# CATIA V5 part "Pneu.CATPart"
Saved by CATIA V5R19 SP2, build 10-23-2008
Part number: Pneu
Bounding box of the stored display mesh (mm): x -10 to 50, y -41.955 to 41.955, z -41.99 to 41.99
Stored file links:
  D:\France\IFMA\IAO\Projet\Pneu.CATPart
  D:\France\IFMA\IAO\Projet\pruangdaja_CAO.CATProduct
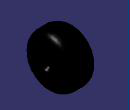
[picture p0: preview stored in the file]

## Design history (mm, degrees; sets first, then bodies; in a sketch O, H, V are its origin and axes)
External parameters (linked from other documents)
  External.Largeur = 10 mm
  External.RayonTrou = 5 mm
Set1
  Plane1: type OffsetPt, RefPlane xy-plane, RefPoint Point1
  Sketch1 on Plane1, origin (0, 0, 0), H (1, 0, 0), V (0, 1, 0)
    line L1 (5, -5) -> (5, -27)
    arc A1 centre (20, -27) radius 15 from (5, -27) to (20, -42) ccw
    line L2 (24.866, -40.5) -> (25.7321, -42)
    line L3 (25.7321, -42) -> (29.2679, -42)
    line L4 (29.2679, -42) -> (30.134, -40.5)
    line L5 (30.134, -40.5) -> (32.134, -40.5)
    line L6 (32.134, -40.5) -> (33, -42)
    point P8 (33, -42)
    line L7 (33, -42) -> (35, -42)
    arc A2 centre (35, -27) radius 15 from (35, -42) to (50, -27) ccw
    line L8 (50, -27) -> (50, -9)
    line L9 (50, -9) -> (45, -4.8111)
    line L10 (45, -4.8111) -> (45, 0)
    point P14 (45, 0)
    line L11 (45, 0) -> (-10, 0)
    line L12 (5, -5) -> (-10, -5)
    line L13 (-10, -5) -> (-10, 0)
    line L14 (20, -42) -> (22, -42)
    point P18 (20, -42)
    line L15 (22, -42) -> (22.866, -40.5)
    line L16 (22.866, -40.5) -> (24.866, -40.5)
    reference projected point E1 (0, 0) from Point1
    length L5 = 2
    radius A2 = 15
    radius A1 = 15
    angle L3 L2 = 120
    angle L3 L4 = 120
    length L13 = 5 {= External.Largeur /2}
    length L1 = 22
    length L8 = 18
    distance L1 L8 = 45
    length L7 = 2
    length L14 = 2
    angle L15 L14 = 120
    distance L14 L16 = 1.5
    distance L5 L7 = 1.5
    angle L6 L7 = 120
    distance L8 L10 = 5
    distance L1 L13 = 15
    distance L13 E1 = 10
    length L16 = 2
    vertical: L1 V, L10 V, L13 V, L8 V
    tangency: A1 L1, L3 A1, L7 A1, A2 L7, L8 A2, L14 A1
    horizontal: L5 H, L11 H, L12 H, L7 H, L14 H
    coincidence: P8 L3, P14 H, P18 L3, P18 A1, P18 L14
Set2
  Plane2: linked copy from another document
  Point1: linked copy from another document
  Line1: linked copy from another document
Body1 (main body)
  Shaft1: profile Sketch1, axis Line1, angle 360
